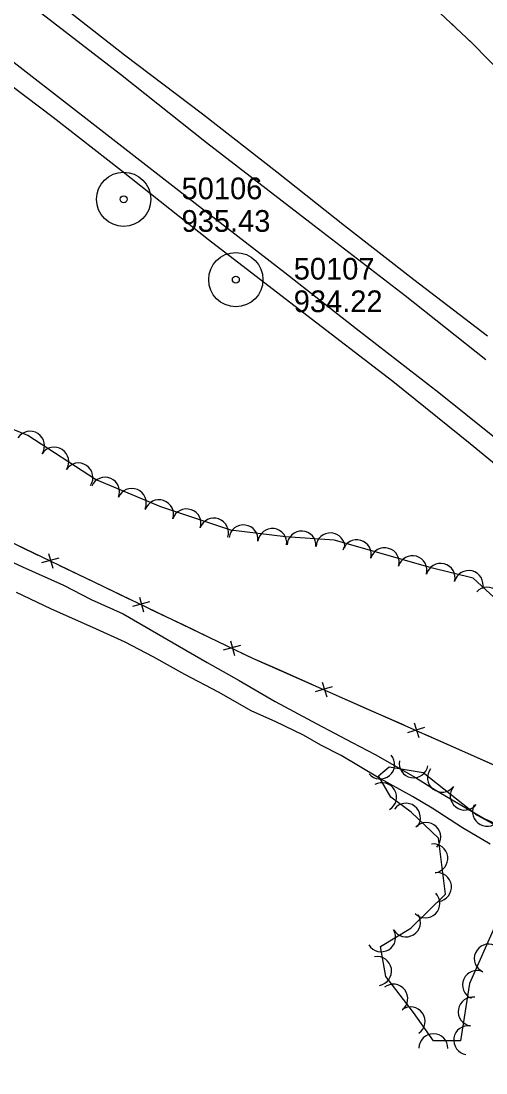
# Model space of a CAD drawing. Extents: x 353423 to 364002, y 127000 to 201942.
# Drawn here: x 359333.6 to 359462, y 131923.3 to 132214.1 of the extents above; entities that cross this region are included whole.
import ezdxf

# ---------------------------------------------------------------- set-up
doc = ezdxf.new("R2010")
doc.units = 0
for name, color, linetype in [('E_DTM_SlopeBottom', 7, 'Continuous'), ('E_DTM_SlopeTop', 7, 'Continuous'), ('E_FEN_Generic', 7, 'Continuous'), ('E_MISCPROP', 7, 'Continuous'), ('E_RDWY_AsphConc', 7, 'Continuous'), ('E_STRUCT_WingWall', 7, 'Continuous')]:
    doc.layers.add(name, color=color, linetype=linetype)

msp = doc.modelspace()

# ---------------------------------------------------------------- linework, layer by layer
at = {"layer": 'E_DTM_SlopeBottom'}
for p, q in [((359343.97, 132065.61), (359339.22, 132064.3)), ((359342.41, 132062.77), (359341.27, 132066.84)), ((359369.08, 132053.54), (359364.32, 132052.23)), ((359367.52, 132050.7), (359366.37, 132054.77)), ((359394.18, 132041.47), (359389.43, 132040.16)), ((359392.63, 132038.62), (359391.48, 132042.69)), ((359419.55, 132030.09), (359414.84, 132028.63)), ((359418.09, 132027.2), (359416.81, 132031.23)), ((359445.03, 132018.82), (359440.32, 132017.36)), ((359443.57, 132015.92), (359442.29, 132019.96))]:
    msp.add_line(p, q, dxfattribs=at)
for points in [[(359733.72, 131713.89), (359702.76, 131754.41), (359666.76, 131801.99), (359626.48, 131855.69), (359595.59, 131897.43), (359560.48, 131944.67), (359539.41, 131973.4), (359530.96, 131978.91), (359397.62, 132037.89), (359310.24, 132079.9), (359248.86, 132107.39), (359167.7, 132142.71), (359107.46, 132171.85), (359029.81, 132208.08), (358952.68, 132209.19), (358924.74, 132208.19)], [(359338.33, 132066.39), (359328.12, 132071.3)], [(359353.23, 132059.23), (359344.26, 132063.54)], [(359363.44, 132054.32), (359353.23, 132059.23)], [(359378.34, 132047.16), (359369.37, 132051.47)], [(359388.54, 132042.25), (359378.34, 132047.16)], [(359403.54, 132035.27), (359397.62, 132037.89), (359394.48, 132039.4)], [(359413.89, 132030.69), (359403.54, 132035.27)], [(359429.02, 132024), (359419.91, 132028.03)], [(359439.37, 132019.42), (359429.02, 132024)], [(359454.49, 132012.73), (359445.39, 132016.76)], [(359464.85, 132008.15), (359454.49, 132012.73)]]:
    msp.add_lwpolyline(points, dxfattribs=at)
at = {"layer": 'E_DTM_SlopeTop'}
for points in [[(359471.36, 132093.36), (359448.96, 132111.3), (359426.1, 132129.02), (359406.4, 132144.54), (359379.62, 132165.25), (359354.79, 132184.61), (359324.59, 132208.03), (359295.17, 132231), (359270.61, 132250.19), (359244, 132270.84), (359216.07, 132292.68), (359188.64, 132314.02), (359159.38, 132336.48), (359129.84, 132359.34)], [(359478.3, 132080.28), (359457.67, 132097.26), (359436.26, 132114.46), (359411.36, 132133.65), (359385.36, 132153.64), (359361.35, 132172.71), (359342.47, 132187.44), (359319.72, 132204.6), (359294.89, 132224.24), (359272.09, 132242.07), (359249.74, 132259.67), (359232.52, 132273.27), (359211.48, 132289.69), (359190.45, 132305.89), (359167.1, 132324.01), (359144.74, 132341.17), (359123.6, 132357.65)], [(359462, 132120.43), (359439.65, 132138.15), (359414.53, 132157.51), (359384.78, 132180.48), (359361.04, 132199.32), (359331.68, 132222.12)], [(359462.44, 132126.97), (359442.12, 132142.6), (359422.91, 132157.45), (359404.21, 132172.34), (359383.67, 132188.37), (359362.14, 132204.68), (359337.58, 132224.04)]]:
    msp.add_lwpolyline(points, dxfattribs=at)
at = {"layer": 'E_FEN_Generic'}
for points in [[(359471.17, 132048.35), (359458.45, 132060.05), (359446.84, 132062.99), (359420.12, 132070.64), (359406.6, 132071.48), (359391.55, 132073.35), (359372.18, 132079.81), (359354.11, 132087.36), (359335.48, 132099.55), (359321.16, 132105.36), (359317.1, 132109.68), (359317.23, 132122.27), (359316.12, 132138.55), (359310.43, 132150.86), (359289.6, 132165.29), (359276.94, 132174.16), (359259.27, 132179.06)], [(359464.71, 131964.42), (359457.42, 131948.05), (359454.94, 131932.15), (359447.49, 131932.23), (359442.01, 131940), (359434.33, 131949.93), (359432.87, 131958.25), (359441.23, 131963.3), (359450.84, 131972.7), (359448.86, 131988.22), (359441.32, 131995.41), (359435.71, 131999.58), (359432.27, 132005.44), (359435.29, 132007.97), (359444.69, 132006.33), (359459.55, 131994.61), (359475.13, 131986.14)]]:
    msp.add_lwpolyline(points, dxfattribs=at)
for centre, start, end in [((359336.04, 132096.69), 326.8046, 146.7893), ((359342.73, 132092.31), 326.8046, 146.7893), ((359349.42, 132087.93), 326.8046, 146.7893), ((359356.78, 132083.98), 337.3137, 157.2984), ((359364.16, 132080.89), 337.3137, 157.2984), ((359371.69, 132077.76), 341.5671, 161.5518), ((359379.28, 132075.23), 341.5671, 161.5518), ((359386.87, 132072.7), 341.5671, 161.5518), ((359395.02, 132070.81), 352.9111, 172.8957), ((359402.96, 132069.82), 352.9111, 172.8957), ((359411.05, 132069.1), 356.4956, 176.4802), ((359419.04, 132068.61), 356.4956, 176.4802), ((359426.32, 132066.69), 344.0306, 164.0153), ((359434.01, 132064.49), 344.0306, 164.0153), ((359441.7, 132062.29), 344.0306, 164.0153), ((359449.47, 132060.17), 345.7551, 165.7398), ((359457.22, 132058.2), 345.7551, 165.7398), ((359462.38, 132053.59), 317.4069, 137.3916), ((359432.77, 132008.59), 219.9954, 39.9801), ((359442.02, 132008.92), 170.1008, 350.0855), ((359449.85, 132004.93), 141.7465, 321.7312), ((359433.29, 131999.56), 300.4816, 120.4663), ((359456.13, 131999.98), 141.7465, 321.7312), ((359439.91, 131993.85), 323.3668, 143.3514), ((359462.3, 131995.5), 151.4681, 331.4528), ((359445.52, 131988.51), 316.392, 136.3767), ((359447.47, 131982.62), 277.2582, 97.2428), ((359448.48, 131974.69), 277.2582, 97.2428), ((359445.28, 131970.19), 224.3941, 44.3788), ((359439.91, 131964.94), 211.1333, 31.118), ((359433.06, 131960.8), 211.1333, 31.118), ((359462.78, 131954.93), 66.0157, 246.0004), ((359431.93, 131951.47), 279.9068, 99.8914), ((359459.52, 131947.62), 66.0157, 246.0004), ((359436.39, 131943.84), 307.7489, 127.7335), ((359458.33, 131940.28), 81.1347, 261.1194), ((359441.17, 131937.55), 305.2318, 125.2165), ((359457.1, 131932.38), 81.1347, 261.1194), ((359447.48, 131930.14), 359.3941, 179.3788)]:
    msp.add_arc(centre, 4, start, end, dxfattribs=at)
at = {"layer": 'E_MISCPROP'}
for points in [[(359325.32, 132067.18), (359333.96, 132063.24)], [(359333.96, 132063.24), (359345.32, 132058.17), (359352.96, 132054.19), (359361.82, 132050.26), (359375.59, 132042.2), (359385, 132036.82), (359393.85, 132031.82), (359403.8, 132025.98), (359415.26, 132019.85), (359425.06, 132014.68), (359431.42, 132011.38), (359442.54, 132004.97), (359447.96, 132001.58), (359455.37, 131997.21), (359461.46, 131993.64), (359466.99, 131991.19)], [(359463.17, 131986.57), (359455.54, 131991.05), (359447.14, 131996.48), (359441.72, 131999.71), (359432.04, 132005.05), (359421.97, 132011.06), (359416.38, 132013.96), (359411.57, 132016.68), (359403.76, 132020.44), (359397.28, 132023.29), (359388.15, 132028.56), (359378.85, 132033.5), (359370.05, 132038.33), (359362.36, 132042.42), (359354.38, 132046.01), (359341.75, 132051.6), (359332.28, 132056.1)]]:
    msp.add_lwpolyline(points, dxfattribs=at)
at = {"layer": 'E_RDWY_AsphConc'}
for centre, radius in [((359361.91, 132164.84), 7.5), ((359361.91, 132164.84), 0.96), ((359392.9, 132142.63), 7.5), ((359392.9, 132142.63), 0.96)]:
    msp.add_circle(centre, radius, dxfattribs=at)
at = {"layer": 'E_STRUCT_WingWall'}
for points in [[(359426.12, 132234.57), (359436.9, 132227.89), (359446.54, 132218.99), (359458.12, 132208.07), (359471.88, 132194.01), (359482.56, 132182.7), (359497.11, 132164.74), (359511.23, 132147.05), (359525.51, 132129.2), (359537.21, 132115.05), (359550.4, 132098.88), (359564.4, 132081.31), (359579.23, 132062.33), (359590.6, 132048.13), (359598.18, 132038.87), (359604.56, 132031.28), (359607.74, 132027.35), (359609.28, 132025.33), (359611.31, 132022.92)], [(359451.78, 132214.05), (359453.23, 132212.68)], [(359456.14, 132209.93), (359457.59, 132208.56)], [(359460.41, 132205.72), (359461.81, 132204.3)]]:
    msp.add_lwpolyline(points, dxfattribs=at)

# ---------------------------------------------------------------- texts
at = {"layer": 'E_RDWY_AsphConc'}
for s, p in [('50106', (359377.91, 132164.84)), ('935.43', (359377.91, 132155.84)), ('50107', (359408.9, 132142.63)), ('934.22', (359408.9, 132133.63))]:
    msp.add_text(s, height=6, dxfattribs=at).set_placement(p)

doc.saveas('drawing.dxf')
